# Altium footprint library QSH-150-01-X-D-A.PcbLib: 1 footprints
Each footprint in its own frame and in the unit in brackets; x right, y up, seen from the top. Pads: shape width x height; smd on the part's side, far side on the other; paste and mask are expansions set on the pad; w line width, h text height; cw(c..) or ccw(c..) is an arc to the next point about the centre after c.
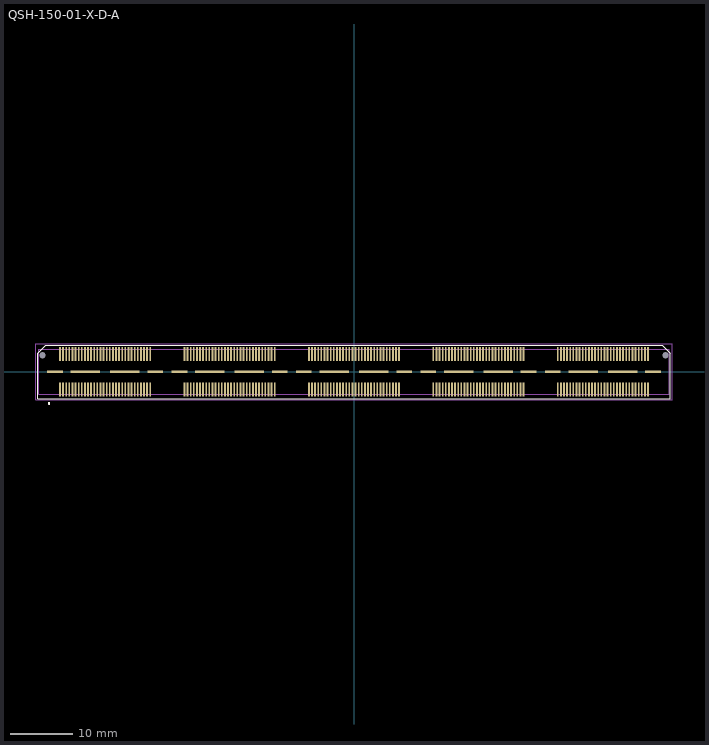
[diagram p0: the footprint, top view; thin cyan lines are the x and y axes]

## QSH-150-01-X-D-A [mm] "0.50mm pitch, 300 pin, high speed socket strip"
height 3.25
pads (322):
  rect 0.28x2.27 smd mask+0: 1(-47.25,-2.87) 2(-47.25,2.87) 3(-46.75,-2.87) 4(-46.75,2.87) 5(-46.25,-2.87) 6(-46.25,2.87) 7(-45.75,-2.87) 8(-45.75,2.87) 9(-45.25,-2.87) 10(-45.25,2.87) 11(-44.75,-2.87) 12(-44.75,2.87) 13(-44.25,-2.87) 14(-44.25,2.87) 15(-43.75,-2.87) 16(-43.75,2.87) 17(-43.25,-2.87) 18(-43.25,2.87) 19(-42.75,-2.87) 20(-42.75,2.87) 21(-42.25,-2.87) 22(-42.25,2.87) 23(-41.75,-2.87) 24(-41.75,2.87) 25(-41.25,-2.87) 26(-41.25,2.87) 27(-40.75,-2.87) 28(-40.75,2.87) 29(-40.25,-2.87) 30(-40.25,2.87) 31(-39.75,-2.87) 32(-39.75,2.87) 33(-39.25,-2.87) 34(-39.25,2.87) 35(-38.75,-2.87) 36(-38.75,2.87) 37(-38.25,-2.87) 38(-38.25,2.87) 39(-37.75,-2.87) 40(-37.75,2.87) 41(-37.25,-2.87) 42(-37.25,2.87) 43(-36.75,-2.87) 44(-36.75,2.87) 45(-36.25,-2.87) 46(-36.25,2.87) 47(-35.75,-2.87) 48(-35.75,2.87) 49(-35.25,-2.87) 50(-35.25,2.87) 51(-34.75,-2.87) 52(-34.75,2.87) 53(-34.25,-2.87) 54(-34.25,2.87) 55(-33.75,-2.87) 56(-33.75,2.87) 57(-33.25,-2.87) 58(-33.25,2.87) 59(-32.75,-2.87) 60(-32.75,2.87) 61(-27.25,-2.87) 62(-27.25,2.87) 63(-26.75,-2.87) 64(-26.75,2.87) 65(-26.25,-2.87) 66(-26.25,2.87) 67(-25.75,-2.87) 68(-25.75,2.87) 69(-25.25,-2.87) 70(-25.25,2.87) 71(-24.75,-2.87) 72(-24.75,2.87) 73(-24.25,-2.87) 74(-24.25,2.87) 75(-23.75,-2.87) 76(-23.75,2.87) 77(-23.25,-2.87) 78(-23.25,2.87) 79(-22.75,-2.87) 80(-22.75,2.87) 81(-22.25,-2.87) 82(-22.25,2.87) 83(-21.75,-2.87) 84(-21.75,2.87) 85(-21.25,-2.87) 86(-21.25,2.87) 87(-20.75,-2.87) 88(-20.75,2.87) 89(-20.25,-2.87) 90(-20.25,2.87) 91(-19.75,-2.87) 92(-19.75,2.87) 93(-19.25,-2.87) 94(-19.25,2.87) 95(-18.75,-2.87) 96(-18.75,2.87) 97(-18.25,-2.87) 98(-18.25,2.87) 99(-17.75,-2.87) 100(-17.75,2.87) 101(-17.25,-2.87) 102(-17.25,2.87) 103(-16.75,-2.87) 104(-16.75,2.87) 105(-16.25,-2.87) 106(-16.25,2.87) 107(-15.75,-2.87) 108(-15.75,2.87) 109(-15.25,-2.87) 110(-15.25,2.87) 111(-14.75,-2.87) 112(-14.75,2.87) 113(-14.25,-2.87) 114(-14.25,2.87) 115(-13.75,-2.87) 116(-13.75,2.87) 117(-13.25,-2.87) 118(-13.25,2.87) 119(-12.75,-2.87) 120(-12.75,2.87) 121(-7.25,-2.87) 122(-7.25,2.87) 123(-6.75,-2.87) 124(-6.75,2.87) 125(-6.25,-2.87) 126(-6.25,2.87) 127(-5.75,-2.87) 128(-5.75,2.87) 129(-5.25,-2.87) 130(-5.25,2.87) 131(-4.75,-2.87) 132(-4.75,2.87) 133(-4.25,-2.87) 134(-4.25,2.87) 135(-3.75,-2.87) 136(-3.75,2.87) 137(-3.25,-2.87) 138(-3.25,2.87) 139(-2.75,-2.87) 140(-2.75,2.87) 141(-2.25,-2.87) 142(-2.25,2.87) 143(-1.75,-2.87) 144(-1.75,2.87) 145(-1.25,-2.87) 146(-1.25,2.87) 147(-0.75,-2.87) 148(-0.75,2.87) 149(-0.25,-2.87) 150(-0.25,2.87) 151(0.25,-2.87) 152(0.25,2.87) 153(0.75,-2.87) 154(0.75,2.87) 155(1.25,-2.87) 156(1.25,2.87) 157(1.75,-2.87) 158(1.75,2.87) 159(2.25,-2.87) 160(2.25,2.87) 161(2.75,-2.87) 162(2.75,2.87) 163(3.25,-2.87) 164(3.25,2.87) 165(3.75,-2.87) 166(3.75,2.87) 167(4.25,-2.87) 168(4.25,2.87) 169(4.75,-2.87) 170(4.75,2.87) 171(5.25,-2.87) 172(5.25,2.87) 173(5.75,-2.87) 174(5.75,2.87) 175(6.25,-2.87) 176(6.25,2.87) 177(6.75,-2.87) 178(6.75,2.87) 179(7.25,-2.87) 180(7.25,2.87) 181(12.75,-2.87) 182(12.75,2.87) 183(13.25,-2.87) 184(13.25,2.87) 185(13.75,-2.87) 186(13.75,2.87) 187(14.25,-2.87) 188(14.25,2.87) 189(14.75,-2.87) 190(14.75,2.87) 191(15.25,-2.87) 192(15.25,2.87) 193(15.75,-2.87) 194(15.75,2.87) 195(16.25,-2.87) 196(16.25,2.87) 197(16.75,-2.87) 198(16.75,2.87) 199(17.25,-2.87) 200(17.25,2.87) 201(17.75,-2.87) 202(17.75,2.87) 203(18.25,-2.87) 204(18.25,2.87) 205(18.75,-2.87) 206(18.75,2.87) 207(19.25,-2.87) 208(19.25,2.87) 209(19.75,-2.87) 210(19.75,2.87) 211(20.25,-2.87) 212(20.25,2.87) 213(20.75,-2.87) 214(20.75,2.87) 215(21.25,-2.87) 216(21.25,2.87) 217(21.75,-2.87) 218(21.75,2.87) 219(22.25,-2.87) 220(22.25,2.87) 221(22.75,-2.87) 222(22.75,2.87) 223(23.25,-2.87) 224(23.25,2.87) 225(23.75,-2.87) 226(23.75,2.87) 227(24.25,-2.87) 228(24.25,2.87) 229(24.75,-2.87) 230(24.75,2.87) 231(25.25,-2.87) 232(25.25,2.87) 233(25.75,-2.87) 234(25.75,2.87) 235(26.25,-2.87) 236(26.25,2.87) 237(26.75,-2.87) 238(26.75,2.87) 239(27.25,-2.87) 240(27.25,2.87) 241(32.75,-2.87) 242(32.75,2.87) 243(33.25,-2.87) 244(33.25,2.87) 245(33.75,-2.87) 246(33.75,2.87) 247(34.25,-2.87) 248(34.25,2.87) 249(34.75,-2.87) 250(34.75,2.87) 251(35.25,-2.87) 252(35.25,2.87) 253(35.75,-2.87) 254(35.75,2.87) 255(36.25,-2.87) 256(36.25,2.87) 257(36.75,-2.87) 258(36.75,2.87) 259(37.25,-2.87) 260(37.25,2.87) 261(37.75,-2.87) 262(37.75,2.87) 263(38.25,-2.87) 264(38.25,2.87) 265(38.75,-2.87) 266(38.75,2.87) 267(39.25,-2.87) 268(39.25,2.87) 269(39.75,-2.87) 270(39.75,2.87) 271(40.25,-2.87) 272(40.25,2.87) 273(40.75,-2.87) 274(40.75,2.87) 275(41.25,-2.87) 276(41.25,2.87) 277(41.75,-2.87) 278(41.75,2.87) 279(42.25,-2.87) 280(42.25,2.87) 281(42.75,-2.87) 282(42.75,2.87) 283(43.25,-2.87) 284(43.25,2.87) 285(43.75,-2.87) 286(43.75,2.87) 287(44.25,-2.87) 288(44.25,2.87) 289(44.75,-2.87) 290(44.75,2.87) 291(45.25,-2.87) 292(45.25,2.87) 293(45.75,-2.87) 294(45.75,2.87) 295(46.25,-2.87) 296(46.25,2.87) 297(46.75,-2.87) 298(46.75,2.87) 299(47.25,-2.87) 300(47.25,2.87)
  rect 2.54x0.43 smd mask+0: 301(-48.065,0) 304(-31.935,0) 305(-28.065,0) 308(-11.935,0) 309(-8.065,0) 312(8.065,0) 313(11.935,0) 316(28.065,0) 317(31.935,0) 320(48.065,0)
  rect 4.7x0.43 smd mask+0: 302(-43.175,0) 303(-36.825,0) 306(-23.175,0) 307(-16.825,0) 310(-3.175,0) 311(3.175,0) 314(16.825,0) 315(23.175,0) 318(36.825,0) 319(43.175,0)
  round 0 hole 1 unplated mask+0: 321(-50.065,2.67) 322(50.065,2.67)
Top Overlay:
  circle w0.2: c-49,-5.076 r0.127
  lines w0.2: -50.85,-4.3 -50.85,3 -49.55,4.3 49.55,4.3 50.85,3 50.85,-4.3 -50.85,-4.3
Mechanical 13:
  circle w0.1: c-49,-5.076 r0.127
  lines w0.1: -50.636,-3.62 -50.636,3.62 50.636,3.62 50.636,-3.62 -50.636,-3.62
  text ".Designator" at 0,0 h1.52
Mechanical 15:
  lines w0.05: -51.136,-4.505 -51.136,4.505 51.136,4.505 51.136,-4.505 -51.136,-4.505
